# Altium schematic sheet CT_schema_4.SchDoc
size 242 x 245 mm
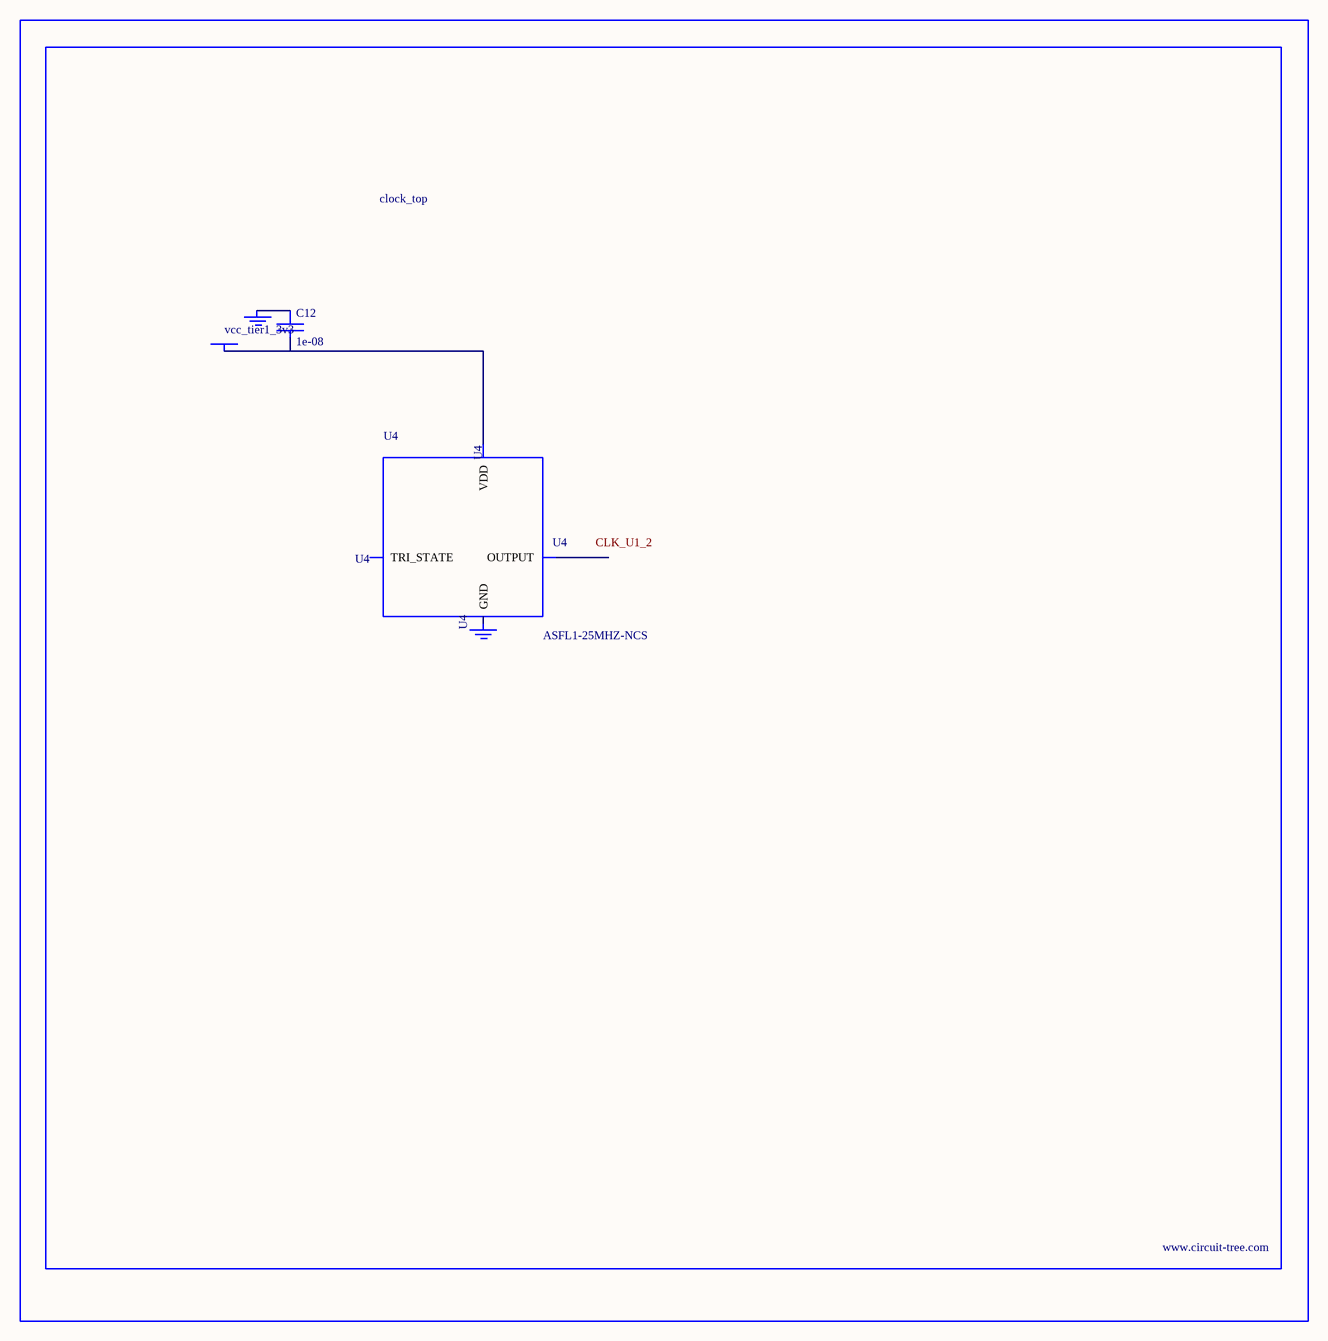
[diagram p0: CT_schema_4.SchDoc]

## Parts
BORDER3  (no value)
C12  1e-08  [C0402]
GND_INSTANCE_3_0  (no value)
GND_INSTANCE_3_1  (no value)
POWER_INSTANCE_3_0  vcc_tier1_3v3
U4  ASFL1-25MHZ-NCS  [ASFL1]

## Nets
NetC12_1: C12.1 GND_INSTANCE_3_0.0(GND)
NetC12_2: C12.2 POWER_INSTANCE_3_0.0(PWR) U4.4(VDD)

Not connected (* = marked no-connect by the designer): GND_INSTANCE_3_1 0(GND); U4 1(TRI_STATE) 2(GND) 3(OUTPUT)

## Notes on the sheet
- Labels drawn without touching a wire or pin: CLK_U1_2

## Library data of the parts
BORDER3 = BORDER_PAGE3
C12 = C0402C103K3RAC
GND_INSTANCE_3_0 GND_INSTANCE_3_1 = GND
POWER_INSTANCE_3_0 = PWR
